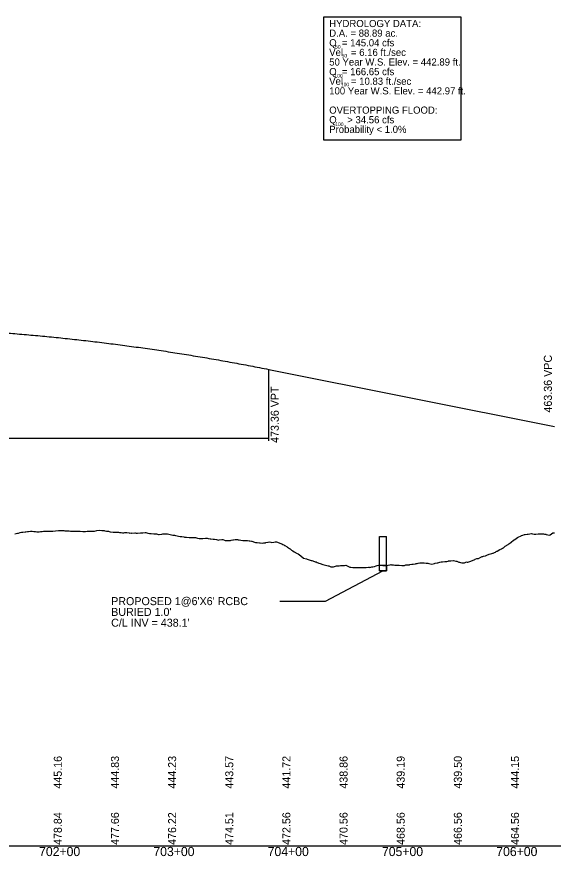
# Model space of a CAD drawing. Extents: x 2017200 to 2047700, y 854850 to 893350.
# Drawn here: x 2023160 to 2023629, y 889091 to 889825 of the extents above; entities that cross this region are included whole.
import ezdxf

# ---------------------------------------------------------------- set-up
doc = ezdxf.new("R2010")
doc.units = 0
for name, color, linetype in [('Culverts', 7, 'Continuous'), ('Default', 7, 'Continuous'), ('RD_DDB_Profile_EX', 7, 'Continuous'), ('RD_DDB_Profile_PR', 7, 'Continuous'), ('RD_DDB_StaTX', 7, 'Continuous'), ('RD_DDB_StripGrade', 7, 'Continuous'), ('RD_DDB_VCLbl', 7, 'Continuous'), ('RD_GPK_Profile_Cell', 7, 'Continuous'), ('RD_PD_DR_Pipe_TX', 7, 'Continuous'), ('RD_PD_Final_TX', 7, 'Continuous')]:
    doc.layers.add(name, color=color, linetype=linetype)

msp = doc.modelspace()

# ---------------------------------------------------------------- linework, layer by layer
at = {"layer": 'Culverts'}
for p, q in [((2023477, 889340.5), (2023477, 889370.5)), ((2023477, 889370.5), (2023483, 889370.5)), ((2023483, 889340.5), (2023483, 889370.5)), ((2023477, 889345.5), (2023483, 889345.5)), ((2023477, 889340.5), (2023483, 889340.5))]:
    msp.add_line(p, q, dxfattribs=at)
msp.add_lwpolyline([(2023477, 889345.5), (2023483, 889345.5), (2023483, 889340.5), (2023477, 889340.5)], close=True, dxfattribs=at)
at = {"layer": 'Default'}
msp.add_lwpolyline([(2023428.25, 889825.36), (2023548.25, 889825.36), (2023548.25, 889717.27), (2023428.25, 889717.27)], close=True, dxfattribs=at)
at = {"layer": 'RD_DDB_Profile_EX'}
msp.add_lwpolyline([(2023157.85, 889372.92), (2023160.23, 889373.46), (2023160.97, 889373.62), (2023162.62, 889374.05), (2023163.77, 889374.29), (2023165, 889374.43), (2023166.97, 889374.75), (2023167.38, 889374.82), (2023168.96, 889375.06), (2023169.77, 889375.1), (2023171.48, 889375.19), (2023172.27, 889375.22), (2023172.99, 889375.33), (2023174.54, 889375.12), (2023175.96, 889374.92), (2023177.03, 889374.74), (2023179.31, 889374.85), (2023180.41, 889374.91), (2023180.77, 889374.96), (2023181.1, 889374.98), (2023181.69, 889375.04), (2023182.89, 889375.17), (2023184.07, 889375.24), (2023184.83, 889375.29), (2023185.19, 889375.3), (2023186.46, 889375.26), (2023188.84, 889375.17), (2023189.3, 889375.15), (2023190.72, 889375.32), (2023191.23, 889375.38), (2023193.61, 889375.66), (2023196, 889375.83), (2023197.91, 889375.92), (2023198.38, 889375.9), (2023200.77, 889375.78), (2023201.77, 889375.73), (2023202.22, 889375.7), (2023203.15, 889375.63), (2023205.53, 889375.46), (2023206.5, 889375.42), (2023207.92, 889375.4), (2023210.3, 889375.37), (2023210.76, 889375.34), (2023212.69, 889375.25), (2023214.46, 889375.17), (2023215.07, 889375.16), (2023217.46, 889375.14), (2023218.74, 889375.12), (2023219.19, 889375.14), (2023219.84, 889375.14), (2023221.09, 889375.15), (2023222.22, 889375.17), (2023223.05, 889375.19), (2023223.37, 889375.18), (2023224.61, 889375.17), (2023226.99, 889375.15), (2023227.53, 889375.17), (2023229.58, 889375.82), (2023231.76, 889376.1), (2023234.15, 889375.94), (2023236.14, 889375.8), (2023236.53, 889375.7), (2023238.07, 889375.32), (2023238.91, 889375.27), (2023239.86, 889375.21), (2023240.56, 889374.99), (2023241.3, 889374.85), (2023243.93, 889374.34), (2023244.44, 889374.3), (2023245.01, 889374.34), (2023246.07, 889374.36), (2023247.97, 889374.38), (2023248.45, 889374.33), (2023249.49, 889374.22), (2023250.84, 889374.06), (2023252, 889373.92), (2023253.22, 889373.96), (2023254, 889374.02), (2023255.6, 889374.02), (2023256.01, 889374.02), (2023257.99, 889373.72), (2023258.55, 889373.64), (2023259.32, 889373.7), (2023259.99, 889373.64), (2023260.37, 889373.67), (2023262.76, 889373.79), (2023263.13, 889373.81), (2023263.96, 889373.66), (2023265.14, 889373.67), (2023267.91, 889373.7), (2023268.83, 889373.79), (2023269.91, 889373.89), (2023271.84, 889374.05), (2023272.39, 889373.99), (2023274.22, 889373.43), (2023274.68, 889373.4), (2023275.75, 889373.35), (2023277.08, 889373.23), (2023279.64, 889372.95), (2023281.83, 889372.84), (2023283.52, 889372.47), (2023284.22, 889372.51), (2023286.6, 889372.66), (2023287.37, 889372.84), (2023289.15, 889372.87), (2023291.37, 889372.87), (2023293.75, 889372.31), (2023295.04, 889372.01), (2023296.21, 889371.87), (2023297.69, 889371.75), (2023298.52, 889371.52), (2023298.85, 889371.43), (2023301.09, 889370.91), (2023302.64, 889370.59), (2023303.29, 889370.6), (2023304.11, 889370.62), (2023305.67, 889370.29), (2023306.42, 889370.18), (2023307.69, 889370.05), (2023308.06, 889370.03), (2023310.44, 889369.87), (2023311, 889369.78), (2023312.83, 889369.71), (2023313.93, 889369.69), (2023315.21, 889369.64), (2023316.02, 889369.61), (2023317.67, 889369.24), (2023319.11, 889369), (2023319.98, 889368.9), (2023321.38, 889368.76), (2023322.36, 889368.9), (2023324.75, 889369.11), (2023325.09, 889369.13), (2023326.21, 889369.11), (2023327.13, 889368.91), (2023328.78, 889368.55), (2023329.52, 889368.47), (2023331.38, 889368.27), (2023331.9, 889368.21), (2023332.46, 889368.15), (2023334.29, 889368.12), (2023336.12, 889367.48), (2023336.67, 889367.63), (2023339.05, 889368.02), (2023339.77, 889368.14), (2023341.44, 889367.32), (2023341.88, 889367.1), (2023342.79, 889367.04), (2023343.41, 889367.18), (2023343.82, 889367.19), (2023346.21, 889367.25), (2023346.65, 889367.26), (2023347.22, 889367.32), (2023348.59, 889367.61), (2023349.27, 889367.75), (2023350.65, 889367.94), (2023350.98, 889367.93), (2023352.62, 889367.86), (2023353.36, 889367.76), (2023354.25, 889367.64), (2023355.74, 889367.44), (2023357.37, 889367.22), (2023358.13, 889367.17), (2023360.51, 889367.12), (2023361.41, 889367.11), (2023362.9, 889366.95), (2023363.61, 889366.88), (2023364.98, 889366.57), (2023365.28, 889366.47), (2023367.67, 889365.66), (2023368.53, 889365.29), (2023369.21, 889365.3), (2023370.05, 889365.27), (2023372.08, 889365.2), (2023372.43, 889365.16), (2023374.87, 889364.9), (2023375.61, 889364.98), (2023377.2, 889365.21), (2023377.51, 889365.25), (2023379.13, 889365.67), (2023379.59, 889365.75), (2023380.61, 889365.92), (2023381.97, 889365.6), (2023382.64, 889365.44), (2023384.36, 889365.75), (2023385.71, 889365.99), (2023386.43, 889365.96), (2023386.74, 889365.85), (2023389.12, 889365), (2023389.63, 889364.82), (2023390.63, 889364.62), (2023391.51, 889364.17), (2023392.33, 889363.75), (2023393.11, 889363.22), (2023393.89, 889362.85), (2023394.21, 889362.7), (2023396.28, 889361.52), (2023396.58, 889361.35), (2023398.31, 889360.05), (2023398.66, 889359.74), (2023400.04, 889358.55), (2023401.05, 889357.97), (2023402.33, 889357.23), (2023403.49, 889356.56), (2023403.81, 889356.4), (2023404.38, 889356.18), (2023405.81, 889355.32), (2023406.93, 889354.65), (2023408.2, 889353.62), (2023410.58, 889351.72), (2023412.97, 889350.98), (2023413.78, 889350.72), (2023415.35, 889350.28), (2023417.2, 889349.74), (2023417.74, 889349.55), (2023420.12, 889348.67), (2023420.6, 889348.49), (2023421.49, 889348.44), (2023422.51, 889347.93), (2023423.18, 889347.58), (2023424, 889347.31), (2023424.92, 889347.01), (2023427.39, 889346.17), (2023429.66, 889345.5), (2023430.77, 889345.31), (2023432.04, 889345.01), (2023432.62, 889344.88), (2023434.43, 889344.17), (2023436.25, 889344.1), (2023436.81, 889344.21), (2023437.5, 889344.35), (2023439.31, 889344.96), (2023440.85, 889344.89), (2023441.58, 889344.97), (2023442.97, 889345.12), (2023444.2, 889345.29), (2023445.39, 889345.35), (2023446.35, 889345.37), (2023447.54, 889345.4), (2023448.73, 889344.87), (2023449.81, 889344.39), (2023451.12, 889343.82), (2023451.85, 889343.81), (2023453.5, 889343.62), (2023454.2, 889343.54), (2023455.03, 889343.55), (2023455.89, 889343.56), (2023456.8, 889343.56), (2023457.51, 889343.48), (2023458.27, 889343.48), (2023460.82, 889343.4), (2023463.04, 889343.52), (2023464.28, 889343.6), (2023465.42, 889343.64), (2023467.42, 889343.7), (2023467.81, 889343.68), (2023468.6, 889343.63), (2023470.19, 889343.99), (2023470.71, 889344.1), (2023471.24, 889344.19), (2023472.58, 889344.52), (2023473.99, 889344.86), (2023474.96, 889345.12), (2023476.16, 889345.43), (2023477.34, 889345.82), (2023478.71, 889345.58), (2023479.73, 889345.37), (2023480.53, 889345.21), (2023482.11, 889345.24), (2023483.8, 889345.37), (2023484.5, 889345.52), (2023486.36, 889345.91), (2023487.05, 889346.01), (2023487.55, 889345.96), (2023489.27, 889345.73), (2023490.3, 889345.6), (2023491.65, 889345.57), (2023493.08, 889345.54), (2023493.55, 889345.47), (2023494.22, 889345.52), (2023496.42, 889345.24), (2023496.78, 889345.2), (2023498.35, 889345.17), (2023498.8, 889345.38), (2023500.01, 889345.94), (2023501.19, 889345.94), (2023502.3, 889345.94), (2023503.24, 889345.98), (2023503.57, 889346.06), (2023505.29, 889346.44), (2023505.96, 889346.47), (2023506.46, 889346.5), (2023508.34, 889346.8), (2023509.1, 889346.92), (2023509.93, 889347.02), (2023510.72, 889347.25), (2023512.26, 889347.64), (2023513.11, 889347.5), (2023514.26, 889347.54), (2023515.49, 889347.48), (2023516.09, 889347.45), (2023517.88, 889347.36), (2023519.34, 889347.28), (2023520.26, 889346.98), (2023522.65, 889346.3), (2023523.95, 889346.63), (2023525.03, 889347.04), (2023525.67, 889347.29), (2023527.41, 889347.6), (2023528.07, 889347.72), (2023528.85, 889347.94), (2023529.8, 889348.2), (2023531, 889348.53), (2023532.18, 889348.57), (2023534.13, 889348.65), (2023534.57, 889348.67), (2023535.2, 889348.7), (2023535.72, 889348.7), (2023536.95, 889349.12), (2023537.27, 889349.22), (2023538.37, 889349.42), (2023538.92, 889349.39), (2023539.34, 889349.44), (2023541.72, 889349.66), (2023543.65, 889349.19), (2023544.1, 889349.08), (2023544.69, 889348.93), (2023546.49, 889348.31), (2023546.84, 889348.19), (2023547.84, 889347.82), (2023548.87, 889347.67), (2023549.98, 889347.52), (2023551.26, 889347.73), (2023552.93, 889348.36), (2023553.64, 889348.3), (2023554.14, 889348.25), (2023556.03, 889348.86), (2023556.82, 889349.12), (2023557.48, 889349.34), (2023558.41, 889349.73), (2023560.41, 889350.57), (2023560.79, 889350.75), (2023561.98, 889351.32), (2023563.18, 889351.45), (2023563.55, 889351.49), (2023565.56, 889352.55), (2023566.67, 889353.06), (2023567.28, 889353.23), (2023567.95, 889353.38), (2023569.8, 889353.79), (2023570.33, 889354.02), (2023570.82, 889354.22), (2023572.92, 889355.19), (2023575.17, 889355.76), (2023576.03, 889355.93), (2023576.52, 889356.15), (2023577.48, 889356.62), (2023578.3, 889357.02), (2023579.15, 889357.47), (2023579.47, 889357.65), (2023579.87, 889357.88), (2023582.26, 889359.25), (2023583.72, 889359.93), (2023584.64, 889360.39), (2023585.36, 889360.76), (2023587.02, 889362.11), (2023587.93, 889362.84), (2023588.46, 889363.13), (2023589.41, 889363.74), (2023589.98, 889364.11), (2023591.79, 889365.4), (2023592.1, 889365.66), (2023594.17, 889367.29), (2023594.65, 889367.66), (2023596.23, 889368.62), (2023596.56, 889368.88), (2023597.75, 889369.83), (2023598.94, 889370.32), (2023600.32, 889370.88), (2023600.83, 889371.26), (2023601.33, 889371.42), (2023602.46, 889371.8), (2023603.92, 889372.28), (2023604.37, 889372.27), (2023606.1, 889372.54), (2023607, 889372.69), (2023608.48, 889372.88), (2023610.08, 889373.19), (2023610.86, 889373.04), (2023612.36, 889372.77), (2023613.25, 889372.81), (2023613.66, 889372.8), (2023615.63, 889372.94), (2023616.31, 889372.99), (2023618.02, 889372.95), (2023619.3, 889372.92), (2023620.4, 889372.82), (2023621.23, 889372.74), (2023622.36, 889372.55), (2023622.79, 889372.47), (2023624.09, 889372.21), (2023625.43, 889371.84), (2023626.31, 889372.07), (2023627.55, 889373.01), (2023628.49, 889373.71), (2023629.94, 889373.92)], dxfattribs=at)
at = {"layer": 'RD_DDB_Profile_PR'}
msp.add_line((2023380, 889516.8), (2023630, 889466.8), dxfattribs=at)
msp.add_spline([(2022580, 889506.8), (2022596, 889510.33), (2022612, 889513.73), (2022628, 889516.99), (2022644, 889520.11), (2022660, 889523.1), (2022676, 889525.95), (2022692, 889528.67), (2022708, 889531.25), (2022724, 889533.69), (2022740, 889536), (2022756, 889538.17), (2022772, 889540.21), (2022788, 889542.11), (2022804, 889543.87), (2022820, 889545.5), (2022836, 889546.99), (2022852, 889548.35), (2022868, 889549.57), (2022884, 889550.65), (2022900, 889551.6), (2022916, 889552.41), (2022932, 889553.09), (2022948, 889553.63), (2022964, 889554.03), (2022980, 889554.3), (2022996, 889554.43), (2023012, 889554.43), (2023028, 889554.29), (2023044, 889554.01), (2023060, 889553.6), (2023076, 889553.05), (2023092, 889552.37), (2023108, 889551.55), (2023124, 889550.59), (2023140, 889549.5), (2023156, 889548.27), (2023172, 889546.91), (2023188, 889545.41), (2023204, 889543.77), (2023220, 889542), (2023236, 889540.09), (2023252, 889538.05), (2023268, 889535.87), (2023284, 889533.55), (2023300, 889531.1), (2023316, 889528.51), (2023332, 889525.79), (2023348, 889522.93), (2023364, 889519.93), (2023380, 889516.8)], degree=3, dxfattribs=at)
at = {"layer": 'RD_DDB_VCLbl'}
for p, q in [((2023380, 889454.3), (2023380, 889516.8)), ((2022580, 889456.8), (2023380, 889456.8))]:
    msp.add_line(p, q, dxfattribs=at)
at = {"layer": 'RD_GPK_Profile_Cell'}
msp.add_line((2020500, 889100), (2027000, 889100), dxfattribs=at)
at = {"layer": 'RD_PD_DR_Pipe_TX'}
for p, q in [((2023429.77, 889314.06), (2023480, 889340.5)), ((2023389.77, 889314.06), (2023429.77, 889314.06))]:
    msp.add_line(p, q, dxfattribs=at)

# ---------------------------------------------------------------- texts
at = {"layer": 'RD_DDB_StaTX'}
for s, p in [('702+00', (2023179.1, 889091)), ('703+00', (2023279.1, 889091)), ('704+00', (2023379.1, 889091)), ('705+00', (2023479.1, 889091)), ('706+00', (2023579.1, 889091))]:
    msp.add_text(s, height=8, dxfattribs=at).set_placement(p)
at = {"layer": 'RD_DDB_StripGrade'}
for s, p in [('463.36 VPC', (2023627.77, 889479.07)), ('473.36 VPT', (2023388.81, 889452.51)), ('445.16', (2023199, 889150)), ('444.83', (2023249, 889150)), ('444.23', (2023299, 889150)), ('443.57', (2023349, 889150)), ('441.72', (2023399, 889150)), ('438.86', (2023449, 889150)), ('439.19', (2023499, 889150)), ('439.50', (2023549, 889150)), ('444.15', (2023599, 889150)), ('478.84', (2023199, 889100.75)), ('477.66', (2023249, 889100.75)), ('476.22', (2023299, 889100.75)), ('474.51', (2023349, 889100.75)), ('472.56', (2023399, 889100.75)), ('470.56', (2023449, 889100.75)), ('468.56', (2023499, 889100.75)), ('466.56', (2023549, 889100.75)), ('464.56', (2023599, 889100.75))]:
    msp.add_text(s, height=7, rotation=90, dxfattribs=at).set_placement(p)
at = {"layer": 'RD_PD_DR_Pipe_TX'}
for s, p in [("PROPOSED 1@6'X6' RCBC", (2023242.17, 889310.56)), ("BURIED 1.0'", (2023242.17, 889301.13)), ("C/L INV = 438.1'", (2023242.17, 889291.7))]:
    msp.add_text(s, height=7, dxfattribs=at).set_placement(p)
at = {"layer": 'RD_PD_Final_TX'}
for s, height, p in [('HYDROLOGY DATA:', 6.25, (2023432.96, 889816.36)), ('D.A. = 88.89 ac.', 6.25, (2023432.96, 889807.94)), ('Q  = 145.04 cfs', 6.25, (2023432.96, 889799.52)), ('50', 3.125, (2023438.1, 889797.56)), ('Vel   = 6.16 ft./sec', 6.25, (2023432.96, 889791.1)), ('50', 3.125, (2023443.84, 889789.79)), ('50 Year W.S. Elev. = 442.89 ft.', 6.25, (2023432.96, 889782.68)), ('Q  = 166.65 cfs', 6.25, (2023432.96, 889774.27)), ('Vel   = 10.83 ft./sec', 6.25, (2023432.96, 889765.85)), ('100', 3.125, (2023437.5, 889772.22)), ('100 Year W.S. Elev. = 442.97 ft.', 6.25, (2023432.96, 889757.43)), ('100', 3.125, (2023443.22, 889764.56)), ('OVERTOPPING FLOOD:', 6.25, (2023432.96, 889740.59)), ('Q    > 34.56 cfs', 6.25, (2023432.96, 889732.18)), ('100', 3.125, (2023438.25, 889729.8)), ('Probability < 1.0%', 6.25, (2023432.96, 889723.76))]:
    msp.add_text(s, height=height, rotation=360, dxfattribs=at).set_placement(p)

doc.saveas('drawing.dxf')
